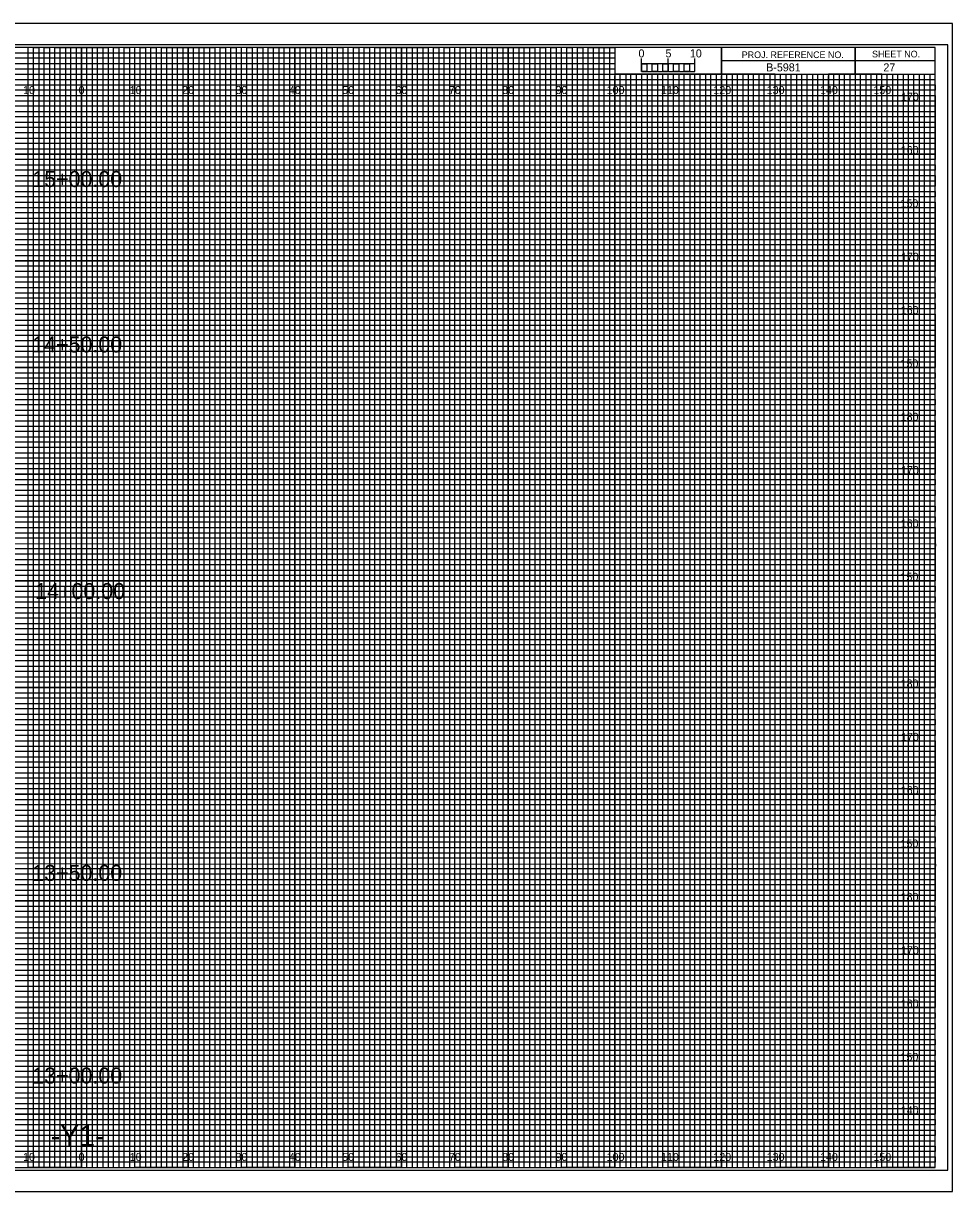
# Model space of a CAD drawing. Extents: x -13 to 323, y -5 to 654.
# Drawn here: x 149.1 to 323.3, y 435.5 to 654.5 of the extents above; entities that cross this region are included whole.
import ezdxf

# ---------------------------------------------------------------- set-up
doc = ezdxf.new("R2010")
doc.units = 0
for name, color, linetype in [('Exist Cross Section Cell', 7, 'Continuous'), ('Exist XS Center Line Elevation Label', 7, 'Continuous'), ('Exist XS Ground Line', 7, 'Continuous'), ('Prop CMT Concrete Structures', 7, 'Continuous'), ('Prop CMT Guardrail Graphics', 7, 'Continuous'), ('Prop CMT Pvmt Course 1', 7, 'Continuous'), ('Prop CMT Pvmt Course 2', 7, 'Continuous'), ('Prop CMT Pvmt Course 3', 7, 'Continuous'), ('Prop CMT Pvmt Surface', 7, 'Continuous'), ('Prop CMT Shld Paved Course 1', 7, 'Continuous'), ('Prop CMT Shld Paved Course 2', 7, 'Continuous'), ('Prop CMT Shld Paved Course 3', 7, 'Continuous'), ('Prop CMT Subgrade Earthwork', 7, 'Continuous'), ('Prop XS Ditch Standard Text', 7, 'Continuous'), ('Prop XS SE Text', 7, 'Continuous'), ('Prop XS Side Slope Text', 7, 'Continuous'), ('Scratch_Level_0', 7, 'Continuous')]:
    doc.layers.add(name, color=color, linetype=linetype)

msp = doc.modelspace()

# ---------------------------------------------------------------- linework, layer by layer
at = {"layer": 'Exist XS Center Line Elevation Label'}
for points in [[(145, 440), (155, 440), (155, 650), (165, 650), (165, 440), (175, 440), (175, 650), (185, 650), (185, 440), (195, 440), (195, 650), (205, 650), (205, 440), (215, 440), (215, 650), (225, 650), (225, 440), (235, 440), (235, 650), (245, 650), (245, 440), (255, 440), (255, 650), (259.93, 650), (260, 650), (260, 645), (264.99, 645), (264.99, 440), (275, 440), (275, 645), (285, 645), (285, 440), (295, 440), (295, 645), (305, 645), (305, 440), (315, 440), (315, 645)], [(0, 645), (275, 645)], [(0, 625), (320, 625), (320, 635), (0, 635)], [(0, 605), (320, 605), (320, 615), (0, 615)], [(0, 585), (320, 585), (320, 595), (0, 595)], [(0, 565), (320, 565), (320, 575), (0, 575)], [(0, 545), (320, 545), (320, 555), (0, 555)], [(0, 525), (320, 525), (320, 535), (0, 535)], [(0, 505), (320, 505), (320, 515), (0, 515)], [(0, 485), (320, 485), (320, 495), (0, 495)], [(0, 465), (320, 465), (320, 475), (0, 475)], [(0, 445), (320, 445), (320, 455), (0, 455)]]:
    msp.add_lwpolyline(points, dxfattribs=at)
at = {"layer": 'Exist XS Ground Line'}
for p, q in [((150, 650), (140, 650)), ((150, 440), (150, 650)), ((170, 650), (160, 650)), ((160, 650), (160, 440)), ((170, 440), (170, 650)), ((190, 650), (180, 650)), ((180, 650), (180, 440)), ((190, 440), (190, 650)), ((210, 650), (200, 650)), ((200, 650), (200, 440)), ((210, 440), (210, 650)), ((230, 650), (220, 650)), ((220, 650), (220, 440)), ((230, 440), (230, 650)), ((250, 650), (240, 650)), ((240, 650), (240, 440)), ((250, 440), (250, 650)), ((260, 650), (260, 440)), ((270, 440), (270, 645)), ((290, 645), (280, 645)), ((280, 645), (280, 440)), ((290, 440), (290, 645)), ((310, 645), (300, 645)), ((300, 645), (300, 440)), ((310, 440), (310, 645)), ((160, 440), (150, 440)), ((180, 440), (170, 440)), ((200, 440), (190, 440)), ((220, 440), (210, 440)), ((240, 440), (230, 440)), ((260, 440), (250, 440)), ((280, 440), (270, 440)), ((300, 440), (290, 440)), ((320, 440), (310, 440)), ((320, 440), (320, 440))]:
    msp.add_line(p, q, dxfattribs=at)
for points in [[(0, 640), (320, 640), (320, 630), (0, 630)], [(0, 620), (320, 620), (320, 610), (0, 610)], [(0, 600), (320, 600), (320, 590), (0, 590)], [(0, 580), (320, 580), (320, 570), (0, 570)], [(0, 560), (320, 560), (320, 550), (0, 550)], [(0, 540), (320, 540), (320, 530), (0, 530)], [(0, 520), (320, 520), (320, 510), (0, 510)], [(0, 500), (320, 500), (320, 490), (0, 490)], [(0, 480), (320, 480), (320, 470), (0, 470)], [(0, 460), (320, 460), (320, 450), (0, 450)]]:
    msp.add_lwpolyline(points, dxfattribs=at)
at = {"layer": 'Prop CMT Pvmt Course 1'}
for p, q in [((323.3, 654.5), (-13.4, 654.5)), ((-13.4, 435.5), (323.3, 435.5))]:
    msp.add_line(p, q, dxfattribs=at)
at = {"layer": 'Prop CMT Pvmt Course 2'}
msp.add_lwpolyline([(-13.4, 435.5), (323.3, 435.5), (323.3, 654.5), (-13.4, 654.5)], close=True, dxfattribs=at)
at = {"layer": 'Prop CMT Pvmt Course 3'}
msp.add_lwpolyline([(-10.8, 439.5), (322.4, 439.5), (322.4, 650.5), (-10.8, 650.5)], close=True, dxfattribs=at)
at = {"layer": 'Prop CMT Shld Paved Course 1'}
for p, q in [((305, 650), (305, 645)), ((305, 645), (305, 650)), ((280, 647.5), (280, 645)), ((320, 647.49), (280, 647.49)), ((280, 645), (320, 645))]:
    msp.add_line(p, q, dxfattribs=at)
for points in [[(320, 650), (0, 650), (0, 440), (320, 440)], [(280, 650), (260, 650), (260, 645.03), (280, 645.03)], [(320, 650), (280, 650), (280, 645), (320, 645)]]:
    msp.add_lwpolyline(points, close=True, dxfattribs=at)
at = {"layer": 'Prop CMT Shld Paved Course 2'}
for p, q in [((267, 645), (266.01, 645)), ((266.01, 645), (266.01, 440)), ((267, 440), (267, 645)), ((269, 645), (268, 645)), ((268, 645), (268, 440)), ((269, 440), (269, 645)), ((266.01, 440), (265, 440)), ((268, 440), (267, 440))]:
    msp.add_line(p, q, dxfattribs=at)
for points in [[(150, 440), (151, 440), (151, 650), (152, 650), (152, 440)], [(152, 440), (153, 440), (153, 650), (154, 650), (154, 440)], [(155, 440), (156, 440), (156, 650), (157, 650), (157, 440)], [(157, 440), (158, 440), (158, 650), (159, 650), (159, 440)], [(160, 440), (161, 440), (161, 650), (162, 650), (162, 440)], [(162, 440), (163, 440), (163, 650), (164, 650), (164, 440)], [(165, 440), (166, 440), (166, 650), (167, 650), (167, 440)], [(167, 440), (168, 440), (168, 650), (169, 650), (169, 440)], [(170, 440), (171, 440), (171, 650), (172, 650), (172, 440)], [(172, 440), (173, 440), (173, 650), (174, 650), (174, 440)], [(175, 440), (176, 440), (176, 650), (177, 650), (177, 440)], [(177, 440), (178, 440), (178, 650), (179, 650), (179, 440)], [(180, 440), (181, 440), (181, 650), (182, 650), (182, 440)], [(182, 440), (183, 440), (183, 650), (184, 650), (184, 440)], [(185, 440), (186, 440), (186, 650), (187, 650), (187, 440)], [(187, 440), (188, 440), (188, 650), (189, 650), (189, 440)], [(190, 440), (191, 440), (191, 650), (192, 650), (192, 440)], [(192, 440), (193, 440), (193, 650), (194, 650), (194, 440)], [(195, 440), (196, 440), (196, 650), (197, 650), (197, 440)], [(197, 440), (198, 440), (198, 650), (199, 650), (199, 440)], [(200, 440), (201, 440), (201, 650), (202, 650), (202, 440)], [(202, 440), (203, 440), (203, 650), (204, 650), (204, 440)], [(205, 440), (206, 440), (206, 650), (207, 650), (207, 440)], [(207, 440), (208, 440), (208, 650), (209, 650), (209, 440)], [(210, 440), (211, 440), (211, 650), (212, 650), (212, 440)], [(212, 440), (213, 440), (213, 650), (214, 650), (214, 440)], [(215, 440), (216, 440), (216, 650), (217, 650), (217, 440)], [(217, 440), (218, 440), (218, 650), (219, 650), (219, 440)], [(220, 440), (221, 440), (221, 650), (222, 650), (222, 440)], [(222, 440), (223, 440), (223, 650), (224, 650), (224, 440)], [(225, 440), (226, 440), (226, 650), (227, 650), (227, 440)], [(227, 440), (228, 440), (228, 650), (229, 650), (229, 440)], [(230, 440), (231, 440), (231, 650), (232, 650), (232, 440)], [(232, 440), (233, 440), (233, 650), (234, 650), (234, 440)], [(235, 440), (236, 440), (236, 650), (237, 650), (237, 440)], [(237, 440), (238, 440), (238, 650), (239, 650), (239, 440)], [(240, 440), (241, 440), (241, 650), (242, 650), (242, 440)], [(242, 440), (243, 440), (243, 650), (244, 650), (244, 440)], [(245, 440), (246, 440), (246, 650), (247, 650), (247, 440)], [(247, 440), (248, 440), (248, 650), (249, 650), (249, 440)], [(250, 440), (251, 440), (251, 650), (252, 650), (252, 440)], [(252, 440), (253, 440), (253, 650), (254, 650), (254, 440)], [(255, 440), (256, 440), (256, 650), (257, 650), (257, 440)], [(257, 440), (258, 440), (258, 650), (259, 650), (259, 440)], [(260, 440), (261, 440), (261, 645), (262.02, 645), (262.02, 440)], [(262, 440), (263, 440), (263, 645), (263.99, 645), (263.99, 440)], [(270, 440), (270.98, 440), (270.98, 645), (272, 645), (272, 440)], [(272, 440), (273, 440), (273, 645), (274.05, 645), (274.05, 440)], [(275, 440), (276, 440), (276, 645), (277, 645), (277, 440)], [(277, 440), (278, 440), (278, 645), (279, 645), (279, 440)], [(280, 440), (281, 440), (281, 645), (282, 645), (282, 440)], [(282, 440), (283, 440), (283, 645), (284, 645), (284, 440)], [(285, 440), (286, 440), (286, 645), (287, 645), (287, 440)], [(287, 440), (288, 440), (288, 645), (289, 645), (289, 440)], [(290, 440), (291, 440), (291, 645), (292, 645), (292, 440)], [(292, 440), (293, 440), (293, 645), (294, 645), (294, 440)], [(295, 440), (296, 440), (296, 645), (297, 645), (297, 440)], [(297, 440), (298, 440), (298, 645), (299, 645), (299, 440)], [(300, 440), (301, 440), (301, 645), (302, 645), (302, 440)], [(302, 440), (303, 440), (303, 645), (304, 645), (304, 440)], [(305, 440), (306, 440), (306, 645), (307, 645), (307, 440)], [(307, 440), (308, 440), (308, 645), (309, 645), (309, 440)], [(310, 440), (311, 440), (311, 645), (312, 645), (312, 440)], [(312, 440), (313, 440), (313, 645), (314, 645), (314, 440)], [(315, 440), (316, 440), (316, 645), (317, 645), (317, 440)], [(317, 440), (318, 440), (318, 645), (319, 645), (319, 440)]]:
    msp.add_lwpolyline(points, dxfattribs=at)
at = {"layer": 'Prop CMT Shld Paved Course 3'}
for p, q in [((265, 645.49), (265, 647.9)), ((265, 646.9), (265, 647.9)), ((270, 645.49), (270, 647.9)), ((275, 645.49), (275, 647.9)), ((275, 646.9), (275, 647.9))]:
    msp.add_line(p, q, dxfattribs=at)
for points in [[(275, 646.9), (265, 646.9), (265, 645.49), (275, 645.49)], [(265, 646.9), (266, 646.9), (266, 645.49), (265, 645.49)], [(267, 646.9), (268, 646.9), (268, 645.49), (267, 645.49)], [(269, 646.9), (270, 646.9), (270, 645.49), (269, 645.49)], [(271, 646.9), (272, 646.9), (272, 645.49), (271, 645.49)], [(273, 646.9), (274, 646.9), (274, 645.49), (273, 645.49)]]:
    msp.add_lwpolyline(points, close=True, dxfattribs=at)
at = {"layer": 'Prop CMT Subgrade Earthwork'}
for p, q in [((150, 440), (150, 650)), ((160, 440), (160, 650)), ((170, 440), (170, 650)), ((180, 440), (180, 650)), ((190, 440), (190, 650)), ((200, 440), (200, 650)), ((210, 440), (210, 650)), ((220, 440), (220, 650)), ((230, 440), (230, 650)), ((240, 440), (240, 650)), ((250, 440), (250, 650)), ((260, 440), (260, 644.69)), ((270, 440), (270, 644.69)), ((280, 440), (280, 644.69)), ((290, 440), (290, 644.69)), ((300, 440), (300, 644.69)), ((310, 440), (310, 644.69)), ((0, 640), (320, 640)), ((0, 630), (320, 630)), ((0, 620), (320, 620)), ((0, 610), (320, 610)), ((0, 600), (320, 600)), ((0, 590), (320, 590)), ((0, 580), (320, 580)), ((0, 570), (320, 570)), ((0, 560), (320, 560)), ((0, 550), (320, 550)), ((0, 540), (320, 540)), ((0, 530), (320, 530)), ((0, 520), (320, 520)), ((0, 510), (320, 510)), ((0, 500), (320, 500)), ((0, 490), (320, 490)), ((0, 480), (320, 480)), ((0, 470), (320, 470)), ((0, 460), (320, 460)), ((0, 450), (320, 450))]:
    msp.add_line(p, q, dxfattribs=at)
at = {"layer": 'Scratch_Level_0'}
for p, q in [((0, 649), (260, 649)), ((260, 649), (260, 647.98)), ((260, 647.98), (0, 647.98)), ((0, 647), (260, 647)), ((260, 647), (260, 645.89)), ((260, 645.89), (0, 645.89)), ((0, 644), (320, 644))]:
    msp.add_line(p, q, dxfattribs=at)
for points in [[(0, 643), (270, 643), (320, 643), (320, 642), (0, 642)], [(0, 641), (320, 641), (320, 639), (0, 639)], [(0, 638), (320, 638), (320, 637), (0, 636.98)], [(0, 636), (320, 636), (320, 634), (0, 634)], [(0, 633), (320, 633), (320, 632), (0, 632)], [(0, 631), (320, 631), (320, 629), (0, 629)], [(0, 628), (320, 628), (320, 627), (0, 627)], [(0, 626), (320, 626), (320, 624), (0, 624)], [(0, 623), (320, 623), (320, 622), (0, 622)], [(0, 621), (320, 621), (320, 619), (0, 619)], [(0, 618), (320, 618), (320, 617), (0, 617)], [(0, 616), (320, 616), (320, 613.95), (320, 613), (320, 612), (0, 612)], [(0, 614), (320, 614), (320, 613), (0, 613)], [(0, 611), (320, 611), (320, 609), (0, 609.03)], [(0, 609.03), (320, 609), (320, 608), (0, 608)], [(0, 607), (320, 607), (320, 606), (0, 606)], [(0, 604), (320, 604), (320, 603), (0, 603)], [(0, 602), (320, 602), (320, 601), (0, 601)], [(-0.07, 598.89), (320, 598.89), (320, 597.88), (-0.07, 597.88)], [(0, 597), (320, 597), (320, 596), (0, 596)], [(0, 594), (320, 594), (320, 593), (0, 593)], [(0, 592), (320, 592), (320, 591), (0, 591)], [(0, 589), (320, 589), (320, 588), (0, 588)], [(0, 587), (320, 587), (320, 586), (0, 586)], [(0, 584), (320, 584), (320, 583), (0, 583)], [(0, 582), (320, 582), (320, 581), (0, 581)], [(0, 579), (320, 579), (319.99, 577.98), (0, 578)], [(0, 577), (320, 577), (320, 576), (0, 576)], [(0, 574), (320, 574), (320, 573), (0, 573)], [(0, 572), (320, 572), (320, 571), (0, 571)], [(0, 569), (320, 569), (320, 568), (0, 568)], [(0, 567), (320, 567), (320, 566), (0, 566)], [(0, 564), (320, 564), (320, 563), (0, 563)], [(0, 562), (320, 562), (320, 561), (0, 561)], [(0, 559), (320, 559), (320, 558), (0, 558)], [(0, 556.99), (320.07, 556.91), (320, 556), (0, 556)], [(0, 554), (320, 554), (320, 553), (0, 553)], [(0, 552), (320, 552), (320, 551), (0, 551)], [(0, 549), (320, 549), (320, 548), (0, 548)], [(0, 547), (320, 547), (320, 546), (0, 546)], [(0, 544), (320, 544), (320, 543), (0, 543)], [(0, 542), (320, 542), (320, 541), (0, 541)], [(0, 539), (320, 539), (320, 538), (0, 538)], [(0, 537), (320, 537), (320, 536), (0, 536)], [(0, 534), (320, 534), (320, 533), (0, 533)], [(0, 532), (320, 532), (320, 531), (0, 531)], [(0, 529), (320, 529), (320, 528), (0, 528)], [(0, 527), (320, 527), (320, 526), (0, 526)], [(0, 524), (320, 524), (320, 523), (0, 523)], [(0, 522), (320, 522), (320, 521), (0, 521)], [(0, 519), (320, 519), (319.99, 517.98), (0, 518)], [(0, 517), (320, 517), (320, 516), (0, 516)], [(0, 514), (320, 514), (320, 513), (0, 513)], [(0, 512), (320, 512), (320, 511), (0, 511)], [(0, 509), (320, 509), (320, 508), (0, 508)], [(0, 507), (320, 507), (320, 506), (0, 506)], [(0, 504), (320, 504), (320, 503), (0, 503)], [(0, 502), (320, 502), (320, 501), (0, 501)], [(0, 499), (320, 499), (320, 498), (0, 498)], [(0, 496.99), (320.07, 496.91), (320, 496), (0, 496)], [(0, 494), (320, 494), (320, 493), (0, 493)], [(0, 492), (320, 492), (320, 491), (0, 491)], [(0, 489), (320, 489), (320, 488), (0, 488)], [(0, 487), (320, 487), (320, 486), (0, 486)], [(0, 484), (320, 484), (320, 483), (0, 483)], [(0, 482), (320, 482), (320, 481), (0, 481)], [(0, 479), (320, 479), (320, 478), (0, 478)], [(0, 477), (320, 477), (320, 476), (0, 476)], [(0, 474), (320, 474), (320, 473), (0, 473)], [(0, 472), (320, 472), (320, 471), (0, 471)], [(0, 469), (320, 469), (320, 468), (0, 468)], [(0, 467), (320, 467), (320, 466), (0, 466)], [(0, 464), (320, 464), (320, 463), (0, 463)], [(0, 462), (320, 462), (320, 461), (0, 461)], [(0, 459), (320, 459), (320, 458), (0, 458)], [(0, 457), (320, 457), (320, 456), (0, 456)], [(0, 454), (320, 454), (320, 453), (0, 453)], [(0, 452), (320, 452), (320, 451), (0, 451)], [(0, 449), (320, 449), (320, 448), (0, 448)], [(0, 447), (320, 447), (320, 446), (0, 446)], [(0, 444), (320, 444), (320, 443), (0, 443)], [(0, 442), (320, 442), (320, 441), (0, 441)]]:
    msp.add_lwpolyline(points, dxfattribs=at)

# ---------------------------------------------------------------- texts
at = {"layer": 'Exist Cross Section Cell'}
for s, p in [('10', (149.04, 641.25)), ('0', (159.45, 641.25)), ('0', (159.45, 641.25)), ('10', (169.04, 641.25)), ('20', (178.86, 641.25)), ('30', (188.86, 641.25)), ('40', (198.86, 641.25)), ('50', (208.86, 641.25)), ('60', (218.86, 641.25)), ('70', (228.86, 641.25)), ('80', (238.86, 641.25)), ('90', (248.86, 641.25)), ('100', (258.44, 641.25)), ('110', (268.62, 641.25)), ('120', (278.44, 641.25)), ('130', (288.44, 641.25)), ('140', (298.44, 641.25)), ('150', (308.44, 641.25)), ('10', (149.04, 441.25)), ('0', (159.45, 441.25)), ('0', (159.45, 441.25)), ('10', (169.04, 441.25)), ('20', (178.86, 441.25)), ('30', (188.86, 441.25)), ('40', (198.86, 441.25)), ('50', (208.86, 441.25)), ('60', (218.86, 441.25)), ('70', (228.86, 441.25)), ('80', (238.86, 441.25)), ('90', (248.86, 441.25)), ('100', (258.44, 441.25)), ('110', (268.62, 441.25)), ('120', (278.44, 441.25)), ('130', (288.44, 441.25)), ('140', (298.44, 441.25)), ('150', (308.44, 441.25))]:
    msp.add_text(s, height=1.5, dxfattribs=at).set_placement(p)
at = {"layer": 'Prop CMT Concrete Structures'}
for s, p in [('15+00.00', (150.77, 623.82)), ('14+50.00', (150.77, 592.81)), ('14+00.00', (151.31, 546.58)), ('13+50.00', (150.77, 493.75)), ('13+00.00', (150.77, 455.76))]:
    msp.add_text(s, height=3, dxfattribs=at).set_placement(p)
at = {"layer": 'Prop CMT Guardrail Graphics'}
for s, p in [('170', (313.61, 640)), ('160', (313.57, 630)), ('150', (313.52, 620)), ('170', (313.61, 610)), ('160', (313.57, 600)), ('150', (313.52, 590)), ('180', (313.55, 580)), ('170', (313.61, 570)), ('160', (313.57, 560)), ('150', (313.52, 550)), ('180', (313.55, 530)), ('170', (313.61, 520)), ('160', (313.57, 510)), ('150', (313.52, 500)), ('180', (313.55, 490)), ('170', (313.61, 480)), ('160', (313.57, 470)), ('150', (313.52, 460)), ('140', (313.57, 450))]:
    msp.add_text(s, height=1.5, dxfattribs=at).set_placement(p)
at = {"layer": 'Prop CMT Pvmt Surface'}
for s, p in [('5', (269.47, 648.12)), ('10', (274.04, 648.12))]:
    msp.add_text(s, height=1.5, dxfattribs=at).set_placement(p)
at = {"layer": 'Prop CMT Shld Paved Course 1'}
for s, p in [('PROJ. REFERENCE NO.', (283.77, 647.99)), ('SHEET NO.', (308.19, 648.12))]:
    msp.add_text(s, height=1.25, dxfattribs=at).set_placement(p)
at = {"layer": 'Prop CMT Shld Paved Course 3'}
msp.add_text('0', height=1.5, dxfattribs=at).set_placement((264.41, 648.12))
at = {"layer": 'Prop XS Ditch Standard Text'}
msp.add_text('-Y1-', height=4, dxfattribs=at).set_placement((154.21, 444))
at = {"layer": 'Prop XS SE Text'}
msp.add_text(' B-5981', height=1.5, dxfattribs=at).set_placement((287.79, 645.5))
at = {"layer": 'Prop XS Side Slope Text'}
msp.add_text('27', height=1.5, dxfattribs=at).set_placement((310.32, 645.5))

doc.saveas('drawing.dxf')
